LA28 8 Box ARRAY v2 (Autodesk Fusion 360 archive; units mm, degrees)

design "LA28 8 Box ARRAY" references "LA28 RF1 Sheet Metal Assembly", "LA28 TOUR BLOCK"
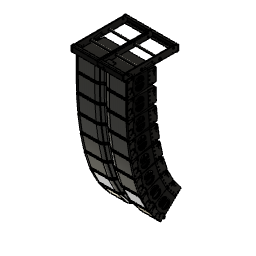
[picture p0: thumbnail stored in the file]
component_insert "Component Insert1" alignAngle -5 alignOffsetX 0 alignOffsetY 0 alignOffsetZ 5.08
as_built_joint "As-built1"
component_insert "Component Insert2"
joint "Assemble1" alignAngle 0 alignOffsetX 0 alignOffsetY 0 alignOffsetZ 5.08
component_insert "Component Insert3"
joint "Assemble2" alignAngle -1 alignOffsetX 0 alignOffsetY 0 alignOffsetZ 5.08
component_insert "Component Insert4"
component_insert "Component Insert5"
joint "Assemble3" alignAngle -3 alignOffsetX 0 alignOffsetY 0 alignOffsetZ 5.08
joint "Assemble4" alignAngle -4 alignOffsetX 0 alignOffsetY 0 alignOffsetZ 5.08
component_insert "Component Insert6"
component_insert "Component Insert7"
component_insert "Component Insert8"
joint "Assemble5" alignAngle -4 alignOffsetX 0 alignOffsetY 0 alignOffsetZ 5.08
joint "Assemble6" alignAngle -6 alignOffsetX 0 alignOffsetY 0 alignOffsetZ 5.08
joint "Assemble7" alignAngle -9 alignOffsetX 0 alignOffsetY 0 alignOffsetZ 5.08
component_insert "Component Insert9"
joint "Assemble8" alignAngle -11 alignOffsetX 0 alignOffsetY 0 alignOffsetZ 5.08

design "la28RF1 SHEET METAL ASSEMBLY.SLDASM"
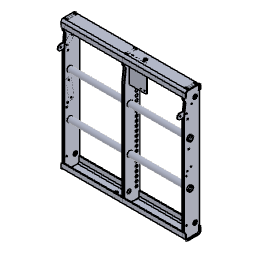
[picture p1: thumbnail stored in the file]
named bodies: "Cut-Extrude3", "Cut-Extrude2", "Mirror2", "Boss-Extrude1"

design "LA28 TOUR BLOCK" references "LA28 TOUR BLOCK.sldprt"
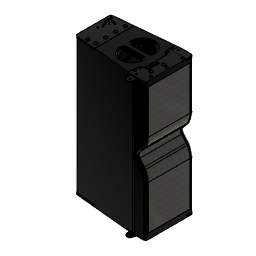
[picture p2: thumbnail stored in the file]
step "WorkingModel"
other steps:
derived_base_feature "Derived Base Feature" bodies "Fillet3"
named bodies: "Fillet3"

design "LA28 RF1 Sheet Metal Assembly" references "la28RF1 SHEET METAL ASSEMBLY.SLDASM"
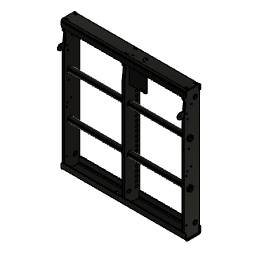
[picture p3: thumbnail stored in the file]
step "WorkingModel"
derived_instance "DerivedInstance1"
derived_instance "DerivedInstance2"
derived_instance "DerivedInstance3"
derived_instance "DerivedInstance4"
derived_instance "DerivedInstance5"
derived_instance "DerivedInstance6"
derived_instance "DerivedInstance7"
as_built_joint "As-built1"
offset_faces "OffsetFaces1" distance 0.7595 (= "0.1644 in - 0.1345 in")
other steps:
derived_base_feature "Derived Base Feature1"
derived_base_feature "Derived Base Feature1" bodies "Cut-Extrude3"
derived_base_feature "Derived Base Feature1" bodies "Cut-Extrude3"
derived_base_feature "Derived Base Feature1" bodies "Boss-Extrude1"
derived_base_feature "Derived Base Feature1" bodies "Cut-Extrude2"
derived_base_feature "Derived Base Feature1" bodies "Boss-Extrude1"
derived_base_feature "Derived Base Feature1" bodies "Cut-Extrude2"
derived_base_feature "Derived Base Feature1" bodies "Mirror2"
create_component "CreateComponent1"
create_component "CreateComponent2"
create_component "CreateComponent3"
create_component "CreateComponent4"
create_component "CreateComponent5"
create_component "CreateComponent6"
create_component "CreateComponent7"
named bodies: "Cut-Extrude3", "Cut-Extrude2", "Mirror2", "Boss-Extrude1"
